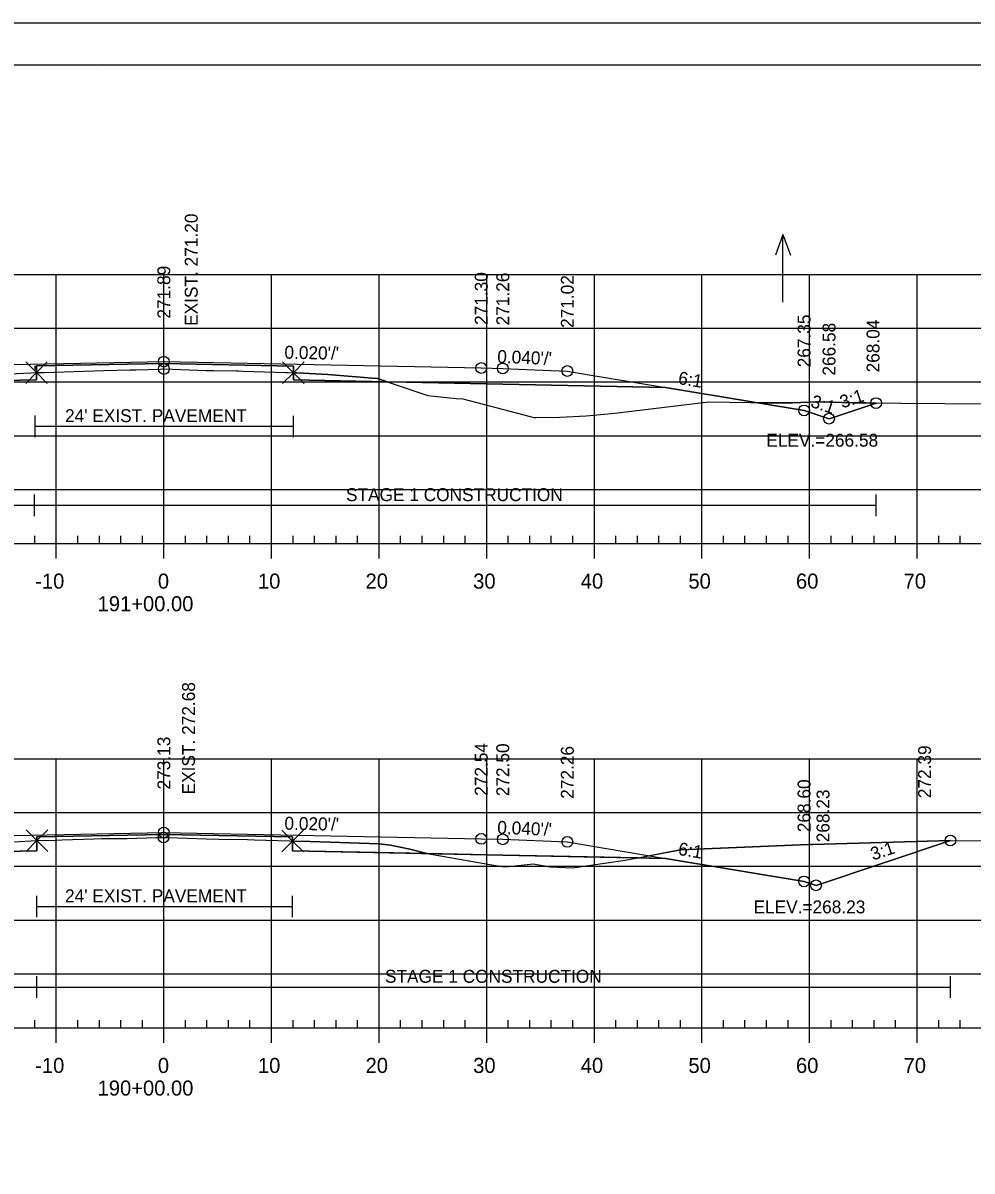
# Model space of a CAD drawing. Extents: x 1365647 to 1367999, y 387113 to 400173.
# Drawn here: x 1365881.8 to 1365970, y 388972.8 to 389079.4 of the extents above; entities that cross this region are included whole.
import ezdxf

# ---------------------------------------------------------------- set-up
doc = ezdxf.new("R2010")
doc.units = 0
for name, color, linetype in [('R_Alt Surface', 7, 'Continuous'), ('R_Axis', 7, 'Continuous'), ('R_Axis Annot', 7, 'Continuous'), ('R_Border', 7, 'Continuous'), ('R_Border Notes', 7, 'Continuous'), ('R_Contours', 7, 'Continuous'), ('R_Exist Surface', 7, 'Continuous'), ('R_Fin Surface', 7, 'Continuous'), ('R_Fin Surface Annot', 7, 'Continuous'), ('R_Grid', 7, 'Continuous'), ('R_No Plot', 7, 'Continuous'), ('R_Proposed Const Limits', 7, 'Continuous'), ('R_Water', 7, 'Continuous'), ('R_Water Annot', 7, 'Continuous'), ('R_Xsect Elev', 7, 'Continuous')]:
    doc.layers.add(name, color=color, linetype=linetype)

msp = doc.modelspace()

# ---------------------------------------------------------------- linework, layer by layer
at = {"layer": 'R_Alt Surface'}
for points in [[(1365848.26, 389045.58), (1365863.38, 389045.88), (1365883.05, 389046.28), (1365883.05, 389047.57), (1365894.88, 389047.8), (1365906.92, 389047.56), (1365906.92, 389046.27), (1365926.38, 389045.88), (1365941.51, 389045.58)], [(1365848.26, 389001.82), (1365863.38, 389002.13), (1365883.09, 389002.52), (1365883.09, 389003.81), (1365894.88, 389004.05), (1365906.85, 389003.81), (1365906.85, 389002.52), (1365926.38, 389002.13), (1365941.51, 389001.82)]]:
    msp.add_lwpolyline(points, dxfattribs=at)
at = {"layer": 'R_Axis'}
for p, q in [((1365882.89, 389031.08), (1365882.89, 389031.78)), ((1365886.89, 389031.08), (1365886.89, 389031.78)), ((1365888.89, 389031.08), (1365888.89, 389031.78)), ((1365890.89, 389031.08), (1365890.89, 389031.78)), ((1365892.89, 389031.08), (1365892.89, 389031.78)), ((1365896.89, 389031.08), (1365896.89, 389031.78)), ((1365898.89, 389031.08), (1365898.89, 389031.78)), ((1365900.89, 389031.08), (1365900.89, 389031.78)), ((1365902.89, 389031.08), (1365902.89, 389031.78)), ((1365906.89, 389031.08), (1365906.89, 389031.78)), ((1365908.89, 389031.08), (1365908.89, 389031.78)), ((1365910.89, 389031.08), (1365910.89, 389031.78)), ((1365912.89, 389031.08), (1365912.89, 389031.78)), ((1365916.89, 389031.08), (1365916.89, 389031.78)), ((1365918.89, 389031.08), (1365918.89, 389031.78)), ((1365920.89, 389031.08), (1365920.89, 389031.78)), ((1365922.89, 389031.08), (1365922.89, 389031.78)), ((1365926.89, 389031.08), (1365926.89, 389031.78)), ((1365928.89, 389031.08), (1365928.89, 389031.78)), ((1365930.89, 389031.08), (1365930.89, 389031.78)), ((1365932.89, 389031.08), (1365932.89, 389031.78)), ((1365936.89, 389031.08), (1365936.89, 389031.78)), ((1365938.89, 389031.08), (1365938.89, 389031.78)), ((1365940.89, 389031.08), (1365940.89, 389031.78)), ((1365942.89, 389031.08), (1365942.89, 389031.78)), ((1365946.89, 389031.08), (1365946.89, 389031.78)), ((1365948.89, 389031.08), (1365948.89, 389031.78)), ((1365950.89, 389031.08), (1365950.89, 389031.78)), ((1365952.89, 389031.08), (1365952.89, 389031.78)), ((1365956.89, 389031.08), (1365956.89, 389031.78)), ((1365958.89, 389031.08), (1365958.89, 389031.78)), ((1365960.89, 389031.08), (1365960.89, 389031.78)), ((1365962.89, 389031.08), (1365962.89, 389031.78)), ((1365966.89, 389031.08), (1365966.89, 389031.78)), ((1365968.89, 389031.08), (1365968.89, 389031.78)), ((1365749.89, 389031.08), (1366039.89, 389031.08)), ((1365884.89, 389029.68), (1365884.89, 389031.08)), ((1365894.89, 389029.68), (1365894.89, 389031.08)), ((1365904.89, 389029.68), (1365904.89, 389031.08)), ((1365914.89, 389029.68), (1365914.89, 389031.08)), ((1365924.89, 389029.68), (1365924.89, 389031.08)), ((1365934.89, 389029.68), (1365934.89, 389031.08)), ((1365944.89, 389029.68), (1365944.89, 389031.08)), ((1365954.89, 389029.68), (1365954.89, 389031.08)), ((1365964.89, 389029.68), (1365964.89, 389031.08)), ((1365749.89, 388986.08), (1366039.89, 388986.08)), ((1365882.89, 388986.08), (1365882.89, 388986.78)), ((1365884.89, 388984.68), (1365884.89, 388986.08)), ((1365886.89, 388986.08), (1365886.89, 388986.78)), ((1365888.89, 388986.08), (1365888.89, 388986.78)), ((1365890.89, 388986.08), (1365890.89, 388986.78)), ((1365892.89, 388986.08), (1365892.89, 388986.78)), ((1365894.89, 388984.68), (1365894.89, 388986.08)), ((1365896.89, 388986.08), (1365896.89, 388986.78)), ((1365898.89, 388986.08), (1365898.89, 388986.78)), ((1365900.89, 388986.08), (1365900.89, 388986.78)), ((1365902.89, 388986.08), (1365902.89, 388986.78)), ((1365904.89, 388984.68), (1365904.89, 388986.08)), ((1365906.89, 388986.08), (1365906.89, 388986.78)), ((1365908.89, 388986.08), (1365908.89, 388986.78)), ((1365910.89, 388986.08), (1365910.89, 388986.78)), ((1365912.89, 388986.08), (1365912.89, 388986.78)), ((1365914.89, 388984.68), (1365914.89, 388986.08)), ((1365916.89, 388986.08), (1365916.89, 388986.78)), ((1365918.89, 388986.08), (1365918.89, 388986.78)), ((1365920.89, 388986.08), (1365920.89, 388986.78)), ((1365922.89, 388986.08), (1365922.89, 388986.78)), ((1365924.89, 388984.68), (1365924.89, 388986.08)), ((1365926.89, 388986.08), (1365926.89, 388986.78)), ((1365928.89, 388986.08), (1365928.89, 388986.78)), ((1365930.89, 388986.08), (1365930.89, 388986.78)), ((1365932.89, 388986.08), (1365932.89, 388986.78)), ((1365934.89, 388984.68), (1365934.89, 388986.08)), ((1365936.89, 388986.08), (1365936.89, 388986.78)), ((1365938.89, 388986.08), (1365938.89, 388986.78)), ((1365940.89, 388986.08), (1365940.89, 388986.78)), ((1365942.89, 388986.08), (1365942.89, 388986.78)), ((1365944.89, 388984.68), (1365944.89, 388986.08)), ((1365946.89, 388986.08), (1365946.89, 388986.78)), ((1365948.89, 388986.08), (1365948.89, 388986.78)), ((1365950.89, 388986.08), (1365950.89, 388986.78)), ((1365952.89, 388986.08), (1365952.89, 388986.78)), ((1365954.89, 388984.68), (1365954.89, 388986.08)), ((1365956.89, 388986.08), (1365956.89, 388986.78)), ((1365958.89, 388986.08), (1365958.89, 388986.78)), ((1365960.89, 388986.08), (1365960.89, 388986.78)), ((1365962.89, 388986.08), (1365962.89, 388986.78)), ((1365964.89, 388984.68), (1365964.89, 388986.08)), ((1365966.89, 388986.08), (1365966.89, 388986.78)), ((1365968.89, 388986.08), (1365968.89, 388986.78))]:
    msp.add_line(p, q, dxfattribs=at)
at = {"layer": 'R_Border'}
for p, q in [((1365736.09, 389075.54), (1366052.27, 389075.54)), ((1365888.61, 389075.28), (1365888.61, 389075.28)), ((1365888.61, 389075.28), (1365888.61, 389075.28))]:
    msp.add_line(p, q, dxfattribs=at)
at = {"layer": 'R_Contours'}
for p, q in [((1365906.92, 389046.94), (1365906.92, 389046.27)), ((1365906.92, 389046.27), (1365915.65, 389046.1)), ((1365950.09, 389044.15), (1365954.38, 389043.44)), ((1365906.85, 389003.43), (1365906.85, 389002.52)), ((1365906.85, 389002.52), (1365919.34, 389002.27)), ((1365940.01, 389002.07), (1365941.51, 389001.82))]:
    msp.add_line(p, q, dxfattribs=at)
for points in [[(1365883.05, 389046.95), (1365883.77, 389046.97), (1365889.31, 389047.15), (1365891.76, 389047.2), (1365892.29, 389047.21), (1365894.56, 389047.28), (1365894.76, 389047.29), (1365894.8, 389047.29), (1365894.89, 389047.29), (1365898.83, 389047.16), (1365899.49, 389047.14), (1365901.59, 389047.11), (1365901.81, 389047.11), (1365902.24, 389047.09), (1365906.26, 389046.96), (1365906.45, 389046.95), (1365906.92, 389046.94), (1365906.92, 389047.56), (1365894.88, 389047.8), (1365883.05, 389047.57)], [(1365873.84, 389046.09), (1365874.3, 389046.23), (1365876.12, 389046.35), (1365877.89, 389046.7), (1365882.53, 389046.92), (1365883.05, 389046.95), (1365883.05, 389046.28)], [(1365906.92, 389046.94), (1365907.25, 389046.93), (1365910.13, 389046.77), (1365914.24, 389046.44), (1365914.77, 389046.39), (1365915.65, 389046.1), (1365906.92, 389046.27)], [(1365915.65, 389046.1), (1365916.38, 389045.86), (1365919.41, 389044.81), (1365922.06, 389044.56), (1365922.68, 389044.5), (1365926.45, 389043.52), (1365928.92, 389042.88), (1365929.29, 389042.78), (1365929.44, 389042.77), (1365931.69, 389042.82), (1365934.14, 389042.92), (1365936.81, 389043.18), (1365945.54, 389044.25), (1365949.41, 389044.16), (1365950.09, 389044.15), (1365941.51, 389045.58), (1365926.38, 389045.88)], [(1365950.09, 389044.15), (1365953.29, 389044.13), (1365955.67, 389044.24), (1365959.02, 389044.14), (1365960.12, 389044.13), (1365961.07, 389044.12), (1365956.7, 389042.67), (1365954.38, 389043.44)], [(1365867.57, 389002.21), (1365871.99, 389002.73), (1365872.93, 389002.89), (1365873.92, 389002.92), (1365876.45, 389003.01), (1365877.83, 389003.19), (1365880.88, 389003.35), (1365883.09, 389003.47), (1365883.09, 389002.52)], [(1365883.09, 389003.47), (1365883.1, 389003.47), (1365884.86, 389003.51), (1365885.4, 389003.53), (1365888.41, 389003.64), (1365889.11, 389003.67), (1365890.86, 389003.67), (1365891.48, 389003.68), (1365894.17, 389003.75), (1365894.74, 389003.76), (1365894.85, 389003.76), (1365894.86, 389003.76), (1365895.28, 389003.75), (1365898.81, 389003.64), (1365899.98, 389003.61), (1365902.67, 389003.56), (1365903.3, 389003.55), (1365906.57, 389003.44), (1365906.85, 389003.43), (1365906.85, 389003.81), (1365894.88, 389004.05), (1365883.09, 389003.81)], [(1365906.85, 389003.43), (1365908.46, 389003.39), (1365910.35, 389003.33), (1365914.87, 389003.16), (1365915.94, 389003.06), (1365917.75, 389002.68), (1365919.21, 389002.29), (1365919.34, 389002.27), (1365906.85, 389002.52)], [(1365938.93, 389001.88), (1365942.91, 389002.61), (1365954.78, 389003.11), (1365954.96, 389003.11), (1365955.04, 389003.11), (1365955.21, 389003.12), (1365967.98, 389003.48), (1365955.49, 388999.31), (1365954.38, 388999.68), (1365941.51, 389001.82)], [(1365919.34, 389002.27), (1365925.17, 389001.24), (1365926.5, 389001.02), (1365926.99, 389001.06), (1365929.21, 389001.3), (1365930.77, 389001.02), (1365932.87, 389000.94), (1365937.76, 389001.66), (1365938.93, 389001.88), (1365926.38, 389002.13)]]:
    msp.add_lwpolyline(points, close=True, dxfattribs=at)
for points in [[(1365915.65, 389046.1), (1365914.77, 389046.39), (1365914.24, 389046.44), (1365910.13, 389046.77), (1365907.25, 389046.93), (1365906.92, 389046.94)], [(1365961.07, 389044.12), (1365960.12, 389044.13), (1365959.02, 389044.14), (1365955.67, 389044.24), (1365953.29, 389044.13), (1365950.09, 389044.15)], [(1365954.38, 389043.44), (1365956.7, 389042.67), (1365961.07, 389044.12)], [(1365919.34, 389002.27), (1365919.21, 389002.29), (1365917.75, 389002.68), (1365915.94, 389003.06), (1365914.87, 389003.16), (1365910.35, 389003.33), (1365908.46, 389003.39), (1365906.85, 389003.43)], [(1365967.98, 389003.48), (1365955.21, 389003.12), (1365955.04, 389003.11), (1365954.96, 389003.11), (1365954.78, 389003.11), (1365942.91, 389002.61), (1365940.01, 389002.07)], [(1365941.51, 389001.82), (1365954.38, 388999.68), (1365955.49, 388999.31), (1365967.98, 389003.48)], [(1365967.98, 389003.48), (1365967.98, 389003.48)]]:
    msp.add_lwpolyline(points, dxfattribs=at)
at = {"layer": 'R_Exist Surface'}
for points in [[(1365877.89, 389046.7), (1365882.53, 389046.92), (1365883.05, 389046.95), (1365883.77, 389046.97), (1365889.31, 389047.15), (1365891.76, 389047.2), (1365892.29, 389047.21), (1365894.56, 389047.28), (1365894.76, 389047.29), (1365894.8, 389047.29), (1365894.89, 389047.29), (1365898.83, 389047.16), (1365899.49, 389047.14), (1365901.59, 389047.11), (1365901.81, 389047.11), (1365902.24, 389047.09), (1365906.26, 389046.96), (1365906.45, 389046.95), (1365906.92, 389046.94), (1365907.25, 389046.93), (1365910.13, 389046.77), (1365914.24, 389046.44), (1365914.77, 389046.39), (1365916.38, 389045.86), (1365919.41, 389044.81), (1365922.06, 389044.56), (1365922.68, 389044.5), (1365926.45, 389043.52), (1365928.92, 389042.88), (1365929.29, 389042.78), (1365929.44, 389042.77), (1365931.69, 389042.82), (1365934.14, 389042.92), (1365936.81, 389043.18), (1365945.54, 389044.25), (1365949.41, 389044.16), (1365953.29, 389044.13), (1365955.67, 389044.24), (1365959.02, 389044.14), (1365960.12, 389044.13), (1365963.44, 389044.1), (1365971.46, 389044.05)], [(1365880.88, 389003.35), (1365883.09, 389003.47), (1365883.1, 389003.47), (1365884.86, 389003.51), (1365885.4, 389003.53), (1365888.41, 389003.64), (1365889.11, 389003.67), (1365890.86, 389003.67), (1365891.48, 389003.68), (1365894.17, 389003.75), (1365894.74, 389003.76), (1365894.85, 389003.76), (1365894.86, 389003.76), (1365895.28, 389003.75), (1365898.81, 389003.64), (1365899.98, 389003.61), (1365902.67, 389003.56), (1365903.3, 389003.55), (1365906.57, 389003.44), (1365906.85, 389003.43), (1365908.46, 389003.39), (1365910.35, 389003.33), (1365914.87, 389003.16), (1365915.94, 389003.06), (1365917.75, 389002.68), (1365919.21, 389002.29), (1365925.17, 389001.24), (1365926.5, 389001.02), (1365926.99, 389001.06), (1365929.21, 389001.3), (1365930.77, 389001.02), (1365932.87, 389000.94), (1365937.76, 389001.66), (1365942.91, 389002.61), (1365954.78, 389003.11), (1365954.96, 389003.11), (1365955.04, 389003.11), (1365955.21, 389003.12), (1365968, 389003.48), (1365971.69, 389003.44)]]:
    msp.add_lwpolyline(points, dxfattribs=at)
at = {"layer": 'R_Fin Surface'}
for points in [[(1365817.94, 389044.1), (1365827.66, 389040.86), (1365835.38, 389043.44), (1365848.26, 389045.58), (1365857.38, 389047.1), (1365863.38, 389047.34), (1365865.38, 389047.38), (1365894.88, 389047.97), (1365924.38, 389047.38), (1365926.38, 389047.34), (1365932.38, 389047.1), (1365941.51, 389045.58), (1365954.38, 389043.44), (1365956.7, 389042.67), (1365961.07, 389044.12)], [(1365857.38, 389047.1), (1365863.38, 389047.34), (1365865.38, 389047.38), (1365894.88, 389047.97), (1365924.38, 389047.38), (1365926.38, 389047.34), (1365932.38, 389047.1)], [(1365812.41, 389002.09), (1365827.52, 388997.06), (1365835.38, 388999.68), (1365848.26, 389001.82), (1365857.38, 389003.35), (1365863.38, 389003.59), (1365865.38, 389003.63), (1365894.88, 389004.22), (1365924.38, 389003.63), (1365926.38, 389003.59), (1365932.38, 389003.35), (1365941.51, 389001.82), (1365954.38, 388999.68), (1365955.49, 388999.31), (1365967.98, 389003.48)], [(1365857.38, 389003.35), (1365863.38, 389003.59), (1365865.38, 389003.63), (1365894.88, 389004.22), (1365924.38, 389003.63), (1365926.38, 389003.59), (1365932.38, 389003.35)]]:
    msp.add_lwpolyline(points, dxfattribs=at)
at = {"layer": 'R_Grid'}
for p, q in [((1365749.89, 389056.08), (1366039.89, 389056.08)), ((1365884.89, 389031.08), (1365884.89, 389056.08)), ((1365894.89, 389031.08), (1365894.89, 389056.08)), ((1365904.89, 389031.08), (1365904.89, 389056.08)), ((1365914.89, 389031.08), (1365914.89, 389056.08)), ((1365924.89, 389031.08), (1365924.89, 389056.08)), ((1365934.89, 389031.08), (1365934.89, 389056.08)), ((1365944.89, 389031.08), (1365944.89, 389056.08)), ((1365954.89, 389031.08), (1365954.89, 389056.08)), ((1365964.89, 389031.08), (1365964.89, 389056.08)), ((1365749.89, 389051.08), (1366039.89, 389051.08)), ((1365749.89, 389046.08), (1366039.89, 389046.08)), ((1365749.89, 389041.08), (1366039.89, 389041.08)), ((1365749.89, 389036.08), (1366039.89, 389036.08)), ((1365749.89, 389031.08), (1366039.89, 389031.08)), ((1365749.89, 389011.08), (1366039.89, 389011.08)), ((1365884.89, 388986.08), (1365884.89, 389011.08)), ((1365894.89, 388986.08), (1365894.89, 389011.08)), ((1365904.89, 388986.08), (1365904.89, 389011.08)), ((1365914.89, 388986.08), (1365914.89, 389011.08)), ((1365924.89, 388986.08), (1365924.89, 389011.08)), ((1365934.89, 388986.08), (1365934.89, 389011.08)), ((1365944.89, 388986.08), (1365944.89, 389011.08)), ((1365954.89, 388986.08), (1365954.89, 389011.08)), ((1365964.89, 388986.08), (1365964.89, 389011.08)), ((1365749.89, 389006.08), (1366039.89, 389006.08)), ((1365749.89, 389001.08), (1366039.89, 389001.08)), ((1365749.89, 388996.08), (1366039.89, 388996.08)), ((1365749.89, 388991.08), (1366039.89, 388991.08)), ((1365749.89, 388986.08), (1366039.89, 388986.08))]:
    msp.add_line(p, q, dxfattribs=at)
at = {"layer": 'R_No Plot'}
for p, q in [((1365723.69, 389079.44), (1366057.03, 389079.44)), ((1365882.92, 389047.23), (1365882.92, 389047.57))]:
    msp.add_line(p, q, dxfattribs=at)
msp.add_lwpolyline([(1365723.69, 389079.44), (1366057.03, 389079.44), (1366057.03, 388866.1), (1365723.69, 388866.1)], close=True, dxfattribs=at)
for points in [[(1365883.05, 389046.95), (1365882.05, 389047.95), (1365883.05, 389046.95), (1365882.05, 389045.95), (1365883.05, 389046.95), (1365884.05, 389045.95), (1365883.05, 389046.95), (1365884.05, 389047.95)], [(1365906.92, 389046.94), (1365905.92, 389047.94), (1365906.92, 389046.94), (1365905.92, 389045.94), (1365906.92, 389046.94), (1365907.92, 389045.94), (1365906.92, 389046.94), (1365907.92, 389047.94)], [(1365883.09, 389003.47), (1365882.09, 389004.47), (1365883.09, 389003.47), (1365882.09, 389002.47), (1365883.09, 389003.47), (1365884.09, 389002.47), (1365883.09, 389003.47), (1365884.09, 389004.47)], [(1365906.85, 389003.43), (1365905.85, 389004.43), (1365906.85, 389003.43), (1365905.85, 389002.43), (1365906.85, 389003.43), (1365907.85, 389002.43), (1365906.85, 389003.43), (1365907.85, 389004.43)]]:
    msp.add_lwpolyline(points, dxfattribs=at)
for centre in [(1365894.88, 389047.97), (1365894.88, 389047.97), (1365894.88, 389047.97), (1365894.88, 389047.97), (1365894.88, 389047.97), (1365894.89, 389047.29), (1365924.38, 389047.38), (1365924.38, 389047.38), (1365924.38, 389047.38), (1365924.38, 389047.38), (1365924.38, 389047.38), (1365926.38, 389047.34), (1365926.38, 389047.34), (1365926.38, 389047.34), (1365926.38, 389047.34), (1365926.38, 389047.34), (1365932.38, 389047.1), (1365932.38, 389047.1), (1365932.38, 389047.1), (1365932.38, 389047.1), (1365932.38, 389047.1), (1365961.07, 389044.12), (1365961.07, 389044.12), (1365954.38, 389043.44), (1365954.38, 389043.44), (1365954.38, 389043.44), (1365954.38, 389043.44), (1365954.38, 389043.44), (1365956.7, 389042.67), (1365956.7, 389042.67), (1365894.85, 389003.76), (1365894.88, 389004.22), (1365894.88, 389004.22), (1365894.88, 389004.22), (1365894.88, 389004.22), (1365894.88, 389004.22), (1365924.38, 389003.63), (1365924.38, 389003.63), (1365924.38, 389003.63), (1365924.38, 389003.63), (1365924.38, 389003.63), (1365926.38, 389003.59), (1365926.38, 389003.59), (1365926.38, 389003.59), (1365926.38, 389003.59), (1365926.38, 389003.59), (1365932.38, 389003.35), (1365932.38, 389003.35), (1365932.38, 389003.35), (1365932.38, 389003.35), (1365932.38, 389003.35), (1365967.98, 389003.48), (1365967.98, 389003.48), (1365954.38, 388999.68), (1365954.38, 388999.68), (1365954.38, 388999.68), (1365954.38, 388999.68), (1365954.38, 388999.68), (1365955.49, 388999.31), (1365955.49, 388999.31)]:
    msp.add_circle(centre, 0.5, dxfattribs=at)
at = {"layer": 'R_Proposed Const Limits'}
for points in [[(1365956.7, 389042.67), (1365961.07, 389044.12)], [(1365955.49, 388999.31), (1365967.98, 389003.48)]]:
    msp.add_lwpolyline(points, dxfattribs=at)
at = {"layer": 'R_Water'}
for p, q in [((1365882.94, 389040.96), (1365882.94, 389042.96)), ((1365906.94, 389040.95), (1365906.94, 389042.95)), ((1365882.94, 389041.96), (1365906.92, 389041.96)), ((1365882.85, 389033.62), (1365882.85, 389035.62)), ((1365961.07, 389033.62), (1365961.07, 389035.62)), ((1365816.21, 389034.62), (1365882.85, 389034.62)), ((1365882.85, 389034.62), (1365961.07, 389034.62)), ((1365883.09, 388996.35), (1365883.09, 388998.35)), ((1365906.85, 388996.35), (1365906.85, 388998.35)), ((1365883.09, 388997.35), (1365906.85, 388997.35)), ((1365883.09, 388988.86), (1365883.09, 388990.86)), ((1365968, 388988.86), (1365968, 388990.86)), ((1365812.41, 388989.86), (1365883.09, 388989.86)), ((1365883.09, 388989.86), (1365968, 388989.86))]:
    msp.add_line(p, q, dxfattribs=at)
at = {"layer": 'R_Water Annot'}
for p, q in [((1365952.42, 389059.78), (1365951.72, 389057.86)), ((1365952.42, 389053.5), (1365952.42, 389059.78)), ((1365952.42, 389059.78), (1365953.12, 389057.86))]:
    msp.add_line(p, q, dxfattribs=at)

# ---------------------------------------------------------------- texts
at = {"layer": 'R_Axis Annot'}
for s, p in [('-10', (1365882.93, 389026.88)), ('0', (1365894.33, 389026.88)), ('10', (1365903.63, 389026.88)), ('20', (1365913.63, 389026.88)), ('30', (1365923.63, 389026.88)), ('40', (1365933.63, 389026.88)), ('50', (1365943.63, 389026.88)), ('60', (1365953.63, 389026.88)), ('70', (1365963.63, 389026.88)), ('191+00.00', (1365888.73, 389024.78)), ('-10', (1365882.93, 388981.88)), ('0', (1365894.33, 388981.88)), ('10', (1365903.63, 388981.88)), ('20', (1365913.63, 388981.88)), ('30', (1365923.63, 388981.88)), ('40', (1365933.63, 388981.88)), ('50', (1365943.63, 388981.88)), ('60', (1365953.63, 388981.88)), ('70', (1365963.63, 388981.88)), ('190+00.00', (1365888.73, 388979.78))]:
    msp.add_text(s, height=1.4, dxfattribs=at).set_placement(p)
at = {"layer": 'R_Border Notes'}
for s, p in [('ELEV.=266.58', (1365950.87, 389040.07)), ('ELEV.=268.23', (1365949.68, 388996.71))]:
    msp.add_text(s, height=1.2, dxfattribs=at).set_placement(p)
at = {"layer": 'R_Fin Surface Annot'}
for s, rotation, p in [('271.89', 90, (1365895.48, 389051.97)), ('271.89', 90, (1365895.48, 389051.97)), ('271.89', 90, (1365895.48, 389051.97)), ('271.30', 90, (1365924.98, 389051.38)), ('271.30', 90, (1365924.98, 389051.38)), ('271.30', 90, (1365924.98, 389051.38)), ('271.26', 90, (1365926.98, 389051.34)), ('271.26', 90, (1365926.98, 389051.34)), ('271.26', 90, (1365926.98, 389051.34)), ('271.02', 90, (1365932.98, 389051.1)), ('271.02', 90, (1365932.98, 389051.1)), ('271.02', 90, (1365932.98, 389051.1)), ('267.35', 90, (1365954.98, 389047.44)), ('267.35', 90, (1365954.98, 389047.44)), ('267.35', 90, (1365954.98, 389047.44)), ('266.58', 90, (1365957.3, 389046.67)), ('268.04', 90, (1365961.39, 389046.97)), ("0.020'/'", 358.8542, (1365906.08, 389048.25)), ("0.040'/'", 357.7094, (1365925.85, 389047.86)), ('6:1', 350.5377, (1365942.62, 389045.9)), ('3:1', 341.5651, (1365954.91, 389043.79)), ('3:1', 18.4349, (1365957.94, 389043.61)), ('273.13', 90, (1365895.48, 389008.22)), ('273.13', 90, (1365895.48, 389008.22)), ('273.13', 90, (1365895.48, 389008.22)), ('272.54', 90, (1365924.98, 389007.63)), ('272.54', 90, (1365924.98, 389007.63)), ('272.54', 90, (1365924.98, 389007.63)), ('272.50', 90, (1365926.98, 389007.59)), ('272.50', 90, (1365926.98, 389007.59)), ('272.50', 90, (1365926.98, 389007.59)), ('272.26', 90, (1365932.98, 389007.35)), ('272.26', 90, (1365932.98, 389007.35)), ('272.26', 90, (1365932.98, 389007.35)), ('272.39', 90, (1365966.18, 389007.41)), ('268.60', 90, (1365954.98, 389004.25)), ('268.23', 90, (1365956.74, 389003.31)), ("0.020'/'", 358.8542, (1365906.08, 389004.49)), ("0.040'/'", 357.7094, (1365925.85, 389004.11)), ('6:1', 350.5377, (1365942.62, 389002.15)), ('3:1', 18.4349, (1365960.79, 389001.61))]:
    msp.add_text(s, height=1.2, rotation=rotation, dxfattribs=at).set_placement(p)
at = {"layer": 'R_Water'}
for s, p in [("24' EXIST. PAVEMENT", (1365885.7, 389042.35)), ('STAGE 1 CONSTRUCTION', (1365911.81, 389035.01)), ("24' EXIST. PAVEMENT", (1365885.7, 388997.74)), ('STAGE 1 CONSTRUCTION', (1365915.43, 388990.26))]:
    msp.add_text(s, height=1.2, dxfattribs=at).set_placement(p)
at = {"layer": 'R_Xsect Elev'}
for s, p in [('EXIST. 271.20', (1365898.03, 389051.29)), ('EXIST. 272.68', (1365897.78, 389007.76))]:
    msp.add_text(s, height=1.2, rotation=90, dxfattribs=at).set_placement(p)

doc.saveas('drawing.dxf')
